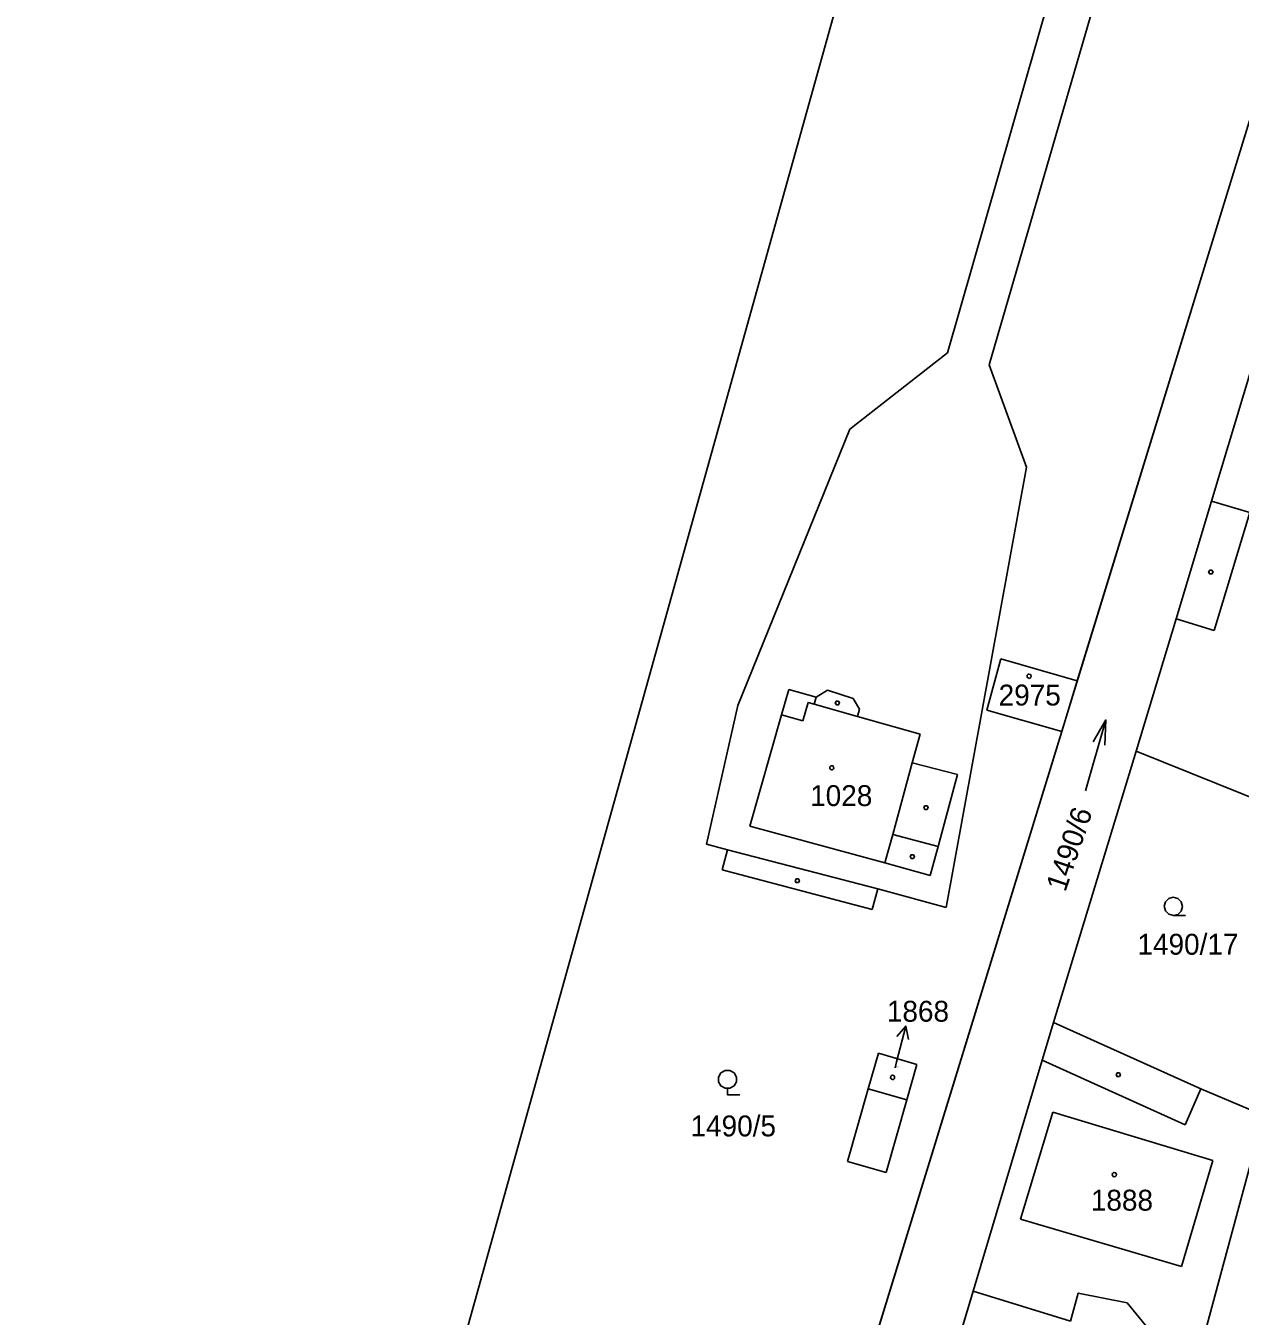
# Model space of a CAD drawing. Extents: x -779618 to -776429, y -1144546 to -1143350.
# Drawn here: x -777658 to -777559.2, y -1143853.5 to -1143748.5 of the extents above; entities that cross this region are included whole.
import ezdxf

# ---------------------------------------------------------------- set-up
doc = ezdxf.new("R2010")
doc.units = 0
for name, color, linetype in [('1', 7, 'Continuous'), ('11', 7, 'Continuous'), ('12', 7, 'Continuous'), ('2', 7, 'Continuous'), ('3', 7, 'Continuous'), ('4', 7, 'Continuous'), ('5', 7, 'Continuous'), ('7', 7, 'Continuous')]:
    doc.layers.add(name, color=color, linetype=linetype)

msp = doc.modelspace()

# ---------------------------------------------------------------- linework, layer by layer
at = {"layer": '1'}
for p, q in [((-777628.63, -1143877.96), (-777586.96, -1143728.55)), ((-777571.45, -1143734.73), (-777583.04, -1143775.14)), ((-777568.02, -1143736.1), (-777579.64, -1143776.1)), ((-777572.48, -1143801.82), (-777554, -1143741.68)), ((-777583.04, -1143775.14), (-777590.98, -1143781.34)), ((-777579.64, -1143776.1), (-777576.59, -1143784.44)), ((-777558.25, -1143776.21), (-777561.56, -1143787.19)), ((-777590.98, -1143781.34), (-777600.08, -1143803.81)), ((-777576.59, -1143784.44), (-777583.15, -1143820.25)), ((-777561.56, -1143787.19), (-777564.44, -1143796.78)), ((-777561.56, -1143787.19), (-777558.44, -1143788.13)), ((-777564.44, -1143796.78), (-777567.68, -1143807.53)), ((-777579.84, -1143804.2), (-777578.68, -1143800.03)), ((-777578.68, -1143800.03), (-777572.48, -1143801.82)), ((-777572.48, -1143801.82), (-777573.74, -1143805.93)), ((-777600.08, -1143803.81), (-777602.62, -1143815.11)), ((-777573.74, -1143805.93), (-777579.84, -1143804.2)), ((-777573.74, -1143805.93), (-777592.84, -1143868.11)), ((-777567.68, -1143807.53), (-777574.4, -1143829.61)), ((-777567.68, -1143807.53), (-777546.02, -1143816.25)), ((-777600.92, -1143815.55), (-777602.62, -1143815.11)), ((-777601.35, -1143817.2), (-777600.92, -1143815.55)), ((-777589.15, -1143820.42), (-777601.35, -1143817.2)), ((-777588.69, -1143818.74), (-777589.15, -1143820.42)), ((-777583.15, -1143820.25), (-777588.69, -1143818.74)), ((-777574.4, -1143829.61), (-777575.32, -1143832.68)), ((-777574.4, -1143829.61), (-777562.42, -1143835.01)), ((-777589.47, -1143835), (-777588.63, -1143832.11)), ((-777588.63, -1143832.11), (-777585.51, -1143833.01)), ((-777585.51, -1143833.01), (-777586.33, -1143835.89)), ((-777575.32, -1143832.68), (-777580.95, -1143851.46)), ((-777591.16, -1143840.91), (-777589.47, -1143835)), ((-777562.42, -1143835.01), (-777545.52, -1143842.15)), ((-777586.33, -1143835.89), (-777588.02, -1143841.81)), ((-777588.02, -1143841.81), (-777591.16, -1143840.91)), ((-777563.57, -1143860.33), (-777558.4, -1143841.22)), ((-777580.95, -1143851.46), (-777585.29, -1143865.94)), ((-777573.03, -1143853.9), (-777580.95, -1143851.46)), ((-777572.39, -1143851.61), (-777573.03, -1143853.9)), ((-777568.41, -1143852.41), (-777572.39, -1143851.61)), ((-777566.21, -1143855.1), (-777568.41, -1143852.41))]:
    msp.add_line(p, q, dxfattribs=at)
at = {"layer": '11'}
msp.add_lwpolyline([(-777835.96, -1143747.19), (-777823.97, -1143691.22), (-777815.03, -1143678.47), (-777780.89, -1143673.92), (-777725.33, -1143676.3), (-777700.17, -1143683.78), (-777654.9, -1143699.9), (-777586.96, -1143728.55), (-777571.45, -1143734.73), (-777568.02, -1143736.1), (-777554, -1143741.68), (-777592.84, -1143868.11), (-777585.29, -1143865.94), (-777580.95, -1143851.46), (-777575.32, -1143832.68), (-777574.4, -1143829.61), (-777567.68, -1143807.53), (-777564.44, -1143796.78), (-777561.56, -1143787.19), (-777558.25, -1143776.21), (-777548.54, -1143741.84), (-777524.39, -1143753.1), (-777521.49, -1143753.86)], dxfattribs=at)
at = {"layer": '12'}
for p, q in [((-777579.84, -1143804.2), (-777578.68, -1143800.03)), ((-777578.68, -1143800.03), (-777572.48, -1143801.82)), ((-777572.48, -1143801.82), (-777573.74, -1143805.93)), ((-777594.8, -1143805.08), (-777594.37, -1143803.58)), ((-777594.37, -1143803.58), (-777593.86, -1143803.72)), ((-777593.86, -1143803.72), (-777590.36, -1143804.71)), ((-777599.1, -1143813.64), (-777596.52, -1143804.59)), ((-777596.52, -1143804.59), (-777594.8, -1143805.08)), ((-777590.36, -1143804.71), (-777585.26, -1143806.15)), ((-777573.74, -1143805.93), (-777579.84, -1143804.2)), ((-777585.26, -1143806.15), (-777585.89, -1143808.48)), ((-777587.48, -1143814.3), (-777585.89, -1143808.48)), ((-777588.12, -1143816.63), (-777599.1, -1143813.64)), ((-777588.12, -1143816.63), (-777587.48, -1143814.3)), ((-777589.47, -1143835), (-777588.63, -1143832.11)), ((-777588.63, -1143832.11), (-777585.51, -1143833.01)), ((-777585.51, -1143833.01), (-777586.33, -1143835.89)), ((-777589.47, -1143835), (-777586.33, -1143835.89)), ((-777577.09, -1143845.59), (-777574.47, -1143836.9)), ((-777574.47, -1143836.9), (-777561.45, -1143840.83)), ((-777561.45, -1143840.83), (-777563.99, -1143849.44)), ((-777563.99, -1143849.44), (-777577.09, -1143845.59))]:
    msp.add_line(p, q, dxfattribs=at)
at = {"layer": '3'}
msp.add_line((-777571.81, -1143810.75), (-777570.15, -1143804.99), dxfattribs=at)
for points in [[(-777571.18, -1143806.77), (-777570.15, -1143804.99), (-777570.22, -1143807.05)], [(-777564.65, -1143820.89), (-777565.03, -1143820.79), (-777565.3, -1143820.52), (-777565.4, -1143820.15), (-777565.3, -1143819.78), (-777565.03, -1143819.51), (-777564.66, -1143819.41), (-777564.29, -1143819.51), (-777564.02, -1143819.78), (-777563.92, -1143820.16), (-777564.02, -1143820.54), (-777564.29, -1143820.81), (-777564.67, -1143820.91), (-777563.67, -1143820.91)], [(-777600.93, -1143834.96), (-777601.12, -1143834.96), (-777601.46, -1143834.77), (-777601.65, -1143834.43), (-777601.65, -1143834.04), (-777601.46, -1143833.7), (-777601.12, -1143833.51), (-777600.73, -1143833.51), (-777600.39, -1143833.7), (-777600.2, -1143834.04), (-777600.2, -1143834.43), (-777600.39, -1143834.77), (-777600.73, -1143834.96), (-777600.92, -1143834.96), (-777600.92, -1143835.49), (-777599.92, -1143835.49)]]:
    msp.add_lwpolyline(points, dxfattribs=at)
at = {"layer": '4'}
for p, q in [((-777561.33, -1143797.71), (-777558.44, -1143788.13)), ((-777564.44, -1143796.78), (-777561.33, -1143797.71)), ((-777596.52, -1143804.59), (-777595.93, -1143802.51)), ((-777595.93, -1143802.51), (-777593.7, -1143803.14)), ((-777593.7, -1143803.14), (-777592.8, -1143802.58)), ((-777592.8, -1143802.58), (-777590.69, -1143803.25)), ((-777594.8, -1143805.08), (-777594.37, -1143803.58)), ((-777594.37, -1143803.58), (-777593.86, -1143803.72)), ((-777593.86, -1143803.72), (-777593.7, -1143803.14)), ((-777593.86, -1143803.72), (-777590.36, -1143804.71)), ((-777590.69, -1143803.25), (-777590.19, -1143804.11)), ((-777590.19, -1143804.11), (-777590.36, -1143804.71)), ((-777599.1, -1143813.64), (-777596.52, -1143804.59)), ((-777596.52, -1143804.59), (-777594.8, -1143805.08)), ((-777590.36, -1143804.71), (-777585.26, -1143806.15)), ((-777585.26, -1143806.15), (-777585.89, -1143808.48)), ((-777587.48, -1143814.3), (-777585.89, -1143808.48)), ((-777585.89, -1143808.48), (-777582.21, -1143809.43)), ((-777582.21, -1143809.43), (-777583.79, -1143815.29)), ((-777588.12, -1143816.63), (-777599.1, -1143813.64)), ((-777588.12, -1143816.63), (-777587.48, -1143814.3)), ((-777587.48, -1143814.3), (-777583.79, -1143815.29)), ((-777600.92, -1143815.55), (-777588.69, -1143818.74)), ((-777583.79, -1143815.29), (-777584.43, -1143817.64)), ((-777584.43, -1143817.64), (-777588.12, -1143816.63)), ((-777575.32, -1143832.68), (-777563.69, -1143837.94)), ((-777589.47, -1143835), (-777586.33, -1143835.89)), ((-777563.69, -1143837.94), (-777562.42, -1143835.01)), ((-777577.09, -1143845.59), (-777574.47, -1143836.9)), ((-777574.47, -1143836.9), (-777561.45, -1143840.83)), ((-777561.45, -1143840.83), (-777563.99, -1143849.44)), ((-777563.99, -1143849.44), (-777577.09, -1143845.59))]:
    msp.add_line(p, q, dxfattribs=at)
at = {"layer": '5'}
for points in [[(-777561.52, -1143792.82), (-777561.43, -1143792.97), (-777561.52, -1143793.12), (-777561.7, -1143793.12), (-777561.79, -1143792.97), (-777561.7, -1143792.82)], [(-777576.39, -1143801.27), (-777576.29, -1143801.29), (-777576.24, -1143801.38), (-777576.22, -1143801.44), (-777576.24, -1143801.53), (-777576.32, -1143801.6), (-777576.39, -1143801.61), (-777576.48, -1143801.58), (-777576.54, -1143801.52), (-777576.56, -1143801.44), (-777576.54, -1143801.35), (-777576.46, -1143801.28)], [(-777591.89, -1143803.46), (-777591.8, -1143803.61), (-777591.89, -1143803.76), (-777592.07, -1143803.76), (-777592.16, -1143803.61), (-777592.07, -1143803.46)], [(-777592.44, -1143808.72), (-777592.34, -1143808.74), (-777592.29, -1143808.83), (-777592.27, -1143808.89), (-777592.29, -1143808.98), (-777592.37, -1143809.05), (-777592.44, -1143809.06), (-777592.53, -1143809.03), (-777592.59, -1143808.97), (-777592.61, -1143808.89), (-777592.59, -1143808.8), (-777592.51, -1143808.73)], [(-777584.69, -1143811.97), (-777584.6, -1143812.12), (-777584.69, -1143812.27), (-777584.87, -1143812.27), (-777584.96, -1143812.12), (-777584.87, -1143811.97)], [(-777585.8, -1143815.96), (-777585.71, -1143816.11), (-777585.8, -1143816.26), (-777585.98, -1143816.26), (-777586.07, -1143816.11), (-777585.98, -1143815.96)], [(-777595.16, -1143817.92), (-777595.07, -1143818.07), (-777595.16, -1143818.22), (-777595.34, -1143818.22), (-777595.43, -1143818.07), (-777595.34, -1143817.92)], [(-777587.5, -1143833.9), (-777587.4, -1143833.92), (-777587.35, -1143834.01), (-777587.33, -1143834.07), (-777587.35, -1143834.16), (-777587.43, -1143834.23), (-777587.5, -1143834.24), (-777587.59, -1143834.21), (-777587.65, -1143834.15), (-777587.67, -1143834.07), (-777587.65, -1143833.98), (-777587.57, -1143833.91)], [(-777569.05, -1143833.71), (-777568.96, -1143833.86), (-777569.05, -1143834.01), (-777569.23, -1143834.01), (-777569.32, -1143833.86), (-777569.23, -1143833.71)], [(-777569.46, -1143841.81), (-777569.36, -1143841.83), (-777569.31, -1143841.92), (-777569.29, -1143841.98), (-777569.31, -1143842.07), (-777569.39, -1143842.14), (-777569.46, -1143842.15), (-777569.55, -1143842.12), (-777569.61, -1143842.06), (-777569.63, -1143841.98), (-777569.61, -1143841.89), (-777569.53, -1143841.82)]]:
    msp.add_lwpolyline(points, close=True, dxfattribs=at)
at = {"layer": '7'}
for p in [(-777586.42, -1143829.89), (-777587.29, -1143833.28)]:
    msp.add_line(p, (-777587.17, -1143832.8), dxfattribs=at)
msp.add_lwpolyline([(-777587.16, -1143830.74), (-777586.42, -1143829.89), (-777586.19, -1143830.99)], dxfattribs=at)

# ---------------------------------------------------------------- texts
at = {"layer": '2'}
for s, height, p in [('2975', 1.7, (-777578.87, -1143803.82)), ('1028', 1.7, (-777594.2, -1143812)), ('1490/17', 1.7, (-777567.58, -1143824.09)), ('1868', 0.1, (-777587.27, -1143833.28)), ('1490/5', 1.7, (-777603.93, -1143838.87)), ('1888', 1.7, (-777571.37, -1143844.91))]:
    msp.add_text(s, height=height, dxfattribs=at).set_placement(p)
msp.add_text('1490/6', height=1.7, rotation=71.3332, dxfattribs=at).set_placement((-777573.44, -1143819.05))
at = {"layer": '7'}
msp.add_text('1868', height=1.7, dxfattribs=at).set_placement((-777587.96, -1143829.54))

doc.saveas('drawing.dxf')
